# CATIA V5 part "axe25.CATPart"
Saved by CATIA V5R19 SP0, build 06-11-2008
Part number: axe25
Publications: "taille_axe"
Bounding box of the stored display mesh (mm): x -5 to 25, y -9 to 9, z -9 to 9
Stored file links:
  H:\EU_thinkMotion\IAO_2010\iao\IAO_MMS_Groupe3\PB\jpeguet\jpeguet_IAO\jpeguet_IAO\axe25.CATPart
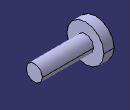
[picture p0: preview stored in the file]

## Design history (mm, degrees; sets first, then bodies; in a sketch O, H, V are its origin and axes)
Parameters
  taille_axe = 25 mm
Body1 (main body)
  Sketch1 on yz-plane, origin (0, 0, 0), H (0, 1, 0), V (0, 0, 1)
    circle A1 centre (0, 0) radius 4
    radius A1 = 4
  Pad1: profile Sketch1, direction (1, 0, 0), length 25 {= taille_axe}
  Sketch2 on start face of Pad1, origin (0, 0, 0), H (0, -1, 0), V (0, 0, 1)
    circle A1 centre (0, 0) radius 9
  Pad2: profile Sketch2, direction (-1, 0, 0), length 5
